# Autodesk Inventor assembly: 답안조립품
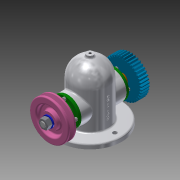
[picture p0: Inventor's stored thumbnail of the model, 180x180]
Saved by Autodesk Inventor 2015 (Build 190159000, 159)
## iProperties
Created: 2019-11
Part Number: 답안조립품
Document SubType Name: Assembly
Designer: now
Author: now
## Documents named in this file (14)
- C:\Users\now\Desktop\491104v1032\답안조립품.iam
- C:\Users\now\Desktop\491104v1032\V-벨트풀리.ipt
- V-벨트풀리.ipt
- C:\Users\now\Desktop\491104v1032\너트 M12x1.25.ipt
- C:\Users\now\Desktop\491104v1032\베어링 6203.ipt
- C:\Users\now\Desktop\491104v1032\본체.ipt
- C:\Users\now\Desktop\491104v1032\볼트 M4.ipt
- C:\Users\now\Desktop\491104v1032\부시.ipt
- C:\Users\now\Desktop\491104v1032\스퍼기어.ipt
- C:\Users\now\Desktop\491104v1032\오일 실 26 38 8.ipt
- C:\Users\now\Desktop\491104v1032\와셔 12x24.ipt
- C:\Users\now\Desktop\491104v1032\축.ipt
- C:\Users\now\Desktop\491104v1032\커버.ipt
- C:\Users\now\Desktop\491104v1032\키 5x5x12.ipt
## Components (1 placed, 1 different names)
1. V-벨트풀리:1 — 각도:4
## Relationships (1: Angle 1)
- 각도:4 [Angle]: V-벨트풀리:1
